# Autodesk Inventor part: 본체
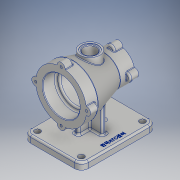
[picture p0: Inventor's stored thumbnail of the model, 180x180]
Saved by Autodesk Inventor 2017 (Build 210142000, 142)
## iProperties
Part Number: 본체
Material: 알루미늄 6061
Document SubType Name: Modeling
Designer: 222
Density: 2.7 g/cm^3
Appearance: 알루미늄 - 평지
Mass: 1029.03 g
Surface Area: 853.297 cm^2
Volume: 381.123 cm^3
Author: 222
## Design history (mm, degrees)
sketch "스케치1"
  geometry: L1 (-50, 0)-(50, 0); L2 (-50, 0)-(-50, 44); L3 (-50, 44)-(-30, 44); L4 (-30, 44)-(25, 27.5); L5 (25, 27.5)-(50, 27.5); L6 (50, 27.5)-(50, 0); 2 further points
  constraints: 12 end point, 2 horizontal, 2 perpendicular, 1 coincident, 1 midpoint, 1 vertical
  dimensions: "d0" = 100 distance of L1.start L1.end; "d1" = 88 diameter of L3 L1; "d2" = 55 diameter of L5 L1; "d3" = 20 distance of L2.end L3.end; "d5" = 25 distance of L4.end L5.end
revolve "회전1" sketch "스케치1" stored, may be unused: angle "d6" = 90 deg
node "작업 평면2"
sketch "스케치2"
  geometry: L1 (65, 50)-(-65, 50); L2 (-65, 50)-(-65, -50); L3 (-65, -50)-(65, -50); L4 (65, -50)-(65, 50); L5 (65, 50)-(-65, -50); L6 (-65, 50)-(65, -50); 1 further point
  constraints: 12 end point, 2 midpoint, 2 parallel, 1 horizontal, 1 perpendicular
  dimensions: "d8" = 130 distance of L2.end L3.end; "d9" = 100 distance of L1.end L2.end
extrude "돌출1" join sketch "스케치2" distance "d10" = 12; taper "d11" = 0 deg
fillet "모깎기1" dims "d12" = 12
sketch "스케치3"
  geometry: A1 r 12 centre (-53, 38) between (-53, 50) and (-65, 38) reference; A2 r 12 centre (53, 38) between (65, 38) and (53, 50) reference; A3 r 12 centre (53, -38) between (53, -50) and (65, -38) reference; A4 r 12 centre (-53, -38) between (-65, -38) and (-53, -50) reference; 1 further point
hole "구멍1" sketch "스케치3" at (-53, 38), (-53, -38), (53, -38), (53, 38) diameter "d13" = 10; stored, may be unused: countersink angle "d17" = 90 deg, drill point angle "d19" = 118 deg; dims "d14" = 6, "d15" = 4, "d16" = 2, "d18" = 8
node "작업 평면3"
sketch "스케치4"
  geometry: C1 r 17 at (0, 0); 1 further point
  constraints: 1 centre point, 1 coincident
  dimensions: "d21" = 34 diameter of C1
extrude "돌출2" join sketch "스케치4" stored distance "d22" = 12; taper "d23" = 0 deg
sketch "스케치11"
  geometry: L1 (-24, -4)-(24, -4); L2 (24, -4)-(24, 4); L3 (24, 4)-(-24, 4); L4 (-24, 4)-(-24, -4); L5 (-24, -4)-(24, 4); L6 (24, -4)-(-24, 4); L7 (-4, -25)-(4, -25); L8 (4, -25)-(4, 25); L9 (4, 25)-(-4, 25); L10 (-4, 25)-(-4, -25); L11 (-4, -25)-(4, 25); L12 (4, -25)-(-4, 25); 1 further point
  constraints: 24 end point, 4 midpoint, 4 parallel, 2 horizontal, 2 perpendicular
  dimensions: "d45" = 8 distance of L1.end L2.end; "d46" = 8 distance of L8.end L9.end; "d47" = 50 distance of L7.end L8.end; "d48" = 48 distance of L2.end L3.end
extrude "돌출8" join sketch "스케치11" stored distance "d49" = 33.5; taper "d50" = 0 deg
sketch "스케치12"
  geometry: C1 r 32 at (0, 0); 1 further point
  constraints: 1 centre point, 1 coincident
  dimensions: "d51" = 64 diameter of C1
extrude "돌출9" cut sketch "스케치12" distance "d52" = 23; taper "d53" = 0 deg
sketch "스케치13"
  geometry: C1 r 26 at (0, 0); 1 further point
  constraints: 1 centre point, 1 coincident
  dimensions: "d54" = 52 diameter of C1
extrude "돌출10" cut sketch "스케치13" distance "d55" = 47; taper "d56" = 0 deg
sketch "스케치14"
  geometry: C1 r 20 at (0, 0); 1 further point
  constraints: 1 centre point, 1 coincident
  dimensions: "d57" = 40 diameter of C1
extrude "돌출11" cut sketch "스케치14" distance "d58" = 30; taper "d59" = 0 deg
chamfer "모따기3" distance "d60" = 1; stored, may be unused: second distance "d61" = 2, angle "d62" = 45 deg
sketch "스케치15"
  geometry: C1 r 14 at (0, 0); 1 further point
  constraints: 1 centre point, 1 coincident
  dimensions: "d63" = 28 diameter of C1
extrude "돌출12" cut sketch "스케치15" distance "d64" = 1; taper "d65" = 0 deg
sketch "스케치16"
  geometry: C1 r 11 at (0, 0); 1 further point
  constraints: 1 centre point, 1 coincident
  dimensions: "d66" = 22 diameter of C1
extrude "돌출13" cut sketch "스케치16" distance "d67" = 25; taper "d68" = 0 deg
chamfer "모따기4" distance "d69" = 1; stored, may be unused: second distance "d70" = 2, angle "d71" = 45 deg
sketch "스케치17"
  geometry: L1 (-14, 44)-(14, 44) reference; A1 r 44 centre (0, 0) between (-6.978, 43.443) and (6.978, 43.443) reference; A2 r 7 centre (0, 44) between (6.978, 43.443) and (-6.978, 43.443); 2 further points
  constraints: 4 point on circle, 1 centre point, 1 coincident, 1 midpoint, 1 vertical alignment
  dimensions: "d72" = 14 diameter of A2
extrude "돌출14" join sketch "스케치17" distance "d73" = 15; taper "d74" = 0 deg
sketch "스케치18"
  geometry: A1 r 7 centre (0, 0) between (6.978, -0.557) and (-6.978, -0.557) reference; 1 further point
hole "구멍2" sketch "스케치18" at (0, 0) diameter "d75" = 4.134; stored, may be unused: countersink angle "d79" = 90 deg, drill point angle "d81" = 118 deg; dims "d76" = 9, "d77" = 4, "d78" = 2, "d80" = 11
sketch "스케치19"
  geometry: A1 r 27.5 centre (0, 0) between (0, 27.5) and (-6.943, 26.609) reference; A2 r 7 centre (0, 27.5) between (6.943, 26.609) and (-6.943, 26.609); 2 further points
  constraints: 5 point on circle, 2 vertical alignment, 1 centre point, 1 coincident, 1 other
  dimensions: "d85" = 14 diameter of A2
extrude "돌출15" join sketch "스케치19" distance "d86" = 15; taper "d87" = 0 deg
sketch "스케치20"
  geometry: A1 r 7 centre (0, 0) between (6.943, -0.891) and (-6.943, -0.891) reference; 1 further point
hole "구멍3" sketch "스케치20" at (0, 0) diameter "d88" = 4.134; stored, may be unused: countersink angle "d92" = 90 deg, drill point angle "d94" = 118 deg; dims "d89" = 9, "d90" = 4, "d91" = 2, "d93" = 11
fillet "모깎기3" dims "d99" = 3
fillet "모깎기4" dims "d100" = 3
fillet "모깎기5" dims "d101" = 1
fillet "모깎기6" dims "d102" = 1
fillet "모깎기7" dims "d103" = 3
fillet "모깎기8" dims "d104" = 3
fillet "모깎기9" dims "d105" = 3
node "작업 평면4"
sketch "스케치21"
  geometry: L1 (-53, -50)-(53, -50) reference; 2 further points
  constraints: 1 vertical alignment, 1 other
  dimensions: "d107" = 10 distance from line of L1 point (0, -40)
feature "엠보싱1" sketch "스케치21" dims "d12" = 12, "d108" = 0.5, "d109" = 0
fillet "모깎기10" dims "d110" = 3
fillet "모깎기11" dims "d111" = 3
fillet "모깎기12" dims "d112" = 1
fillet "모깎기13" dims "d113" = 3
fillet "모깎기14" dims "d114" = 3
node "솔리드1"
pattern_circular "원형 패턴1" dims angle "d83" = 360 deg
pattern_circular "원형 패턴2" dims angle "d96" = 360 deg
other parameters: "d7" = -82, "d20" = 45, "d106" = 27
